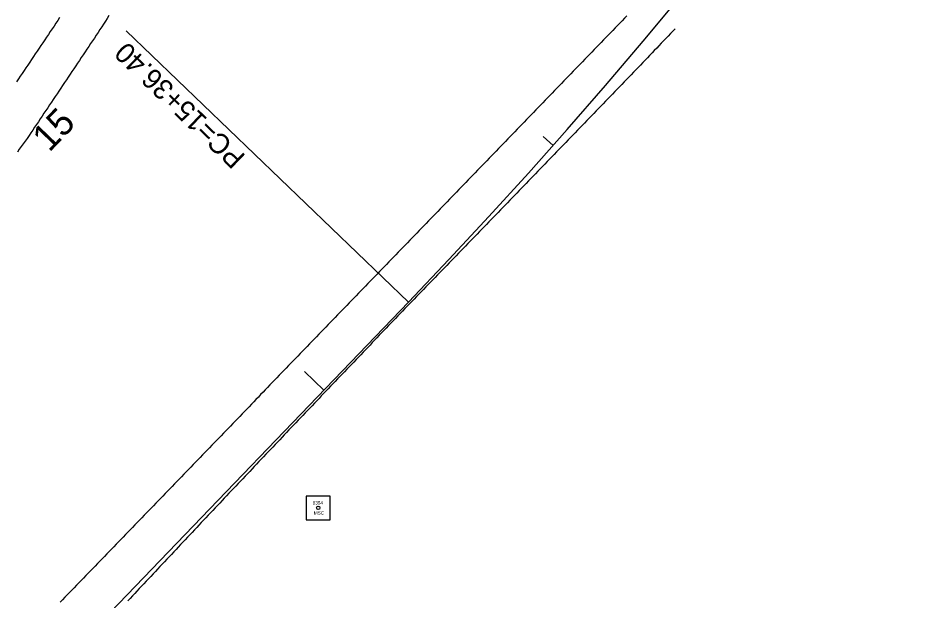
# Model space of a CAD drawing. Extents: x 205929 to 2357175, y -1785700 to 846739.
# Drawn here: x 2013213 to 2013479.6, y 821344.1 to 821517.6 of the extents above; entities that cross this region are included whole.
import ezdxf

# ---------------------------------------------------------------- set-up
doc = ezdxf.new("R2010")
doc.units = 0
for name, color, linetype in [('RD_HC_Cl', 7, 'Continuous'), ('RD_HC_Survey', 7, 'Continuous'), ('RD_HC_txCode', 7, 'Continuous'), ('RD_Sketch1', 7, 'Continuous'), ('RD_SMD_Locator', 7, 'Continuous')]:
    doc.layers.add(name, color=color, linetype=linetype)

msp = doc.modelspace()

# ---------------------------------------------------------------- linework, layer by layer
at = {"layer": 'RD_HC_Cl'}
for p, q in [((2013329.43, 821432.89), (2013245.32, 821513.78)), ((2013372.57, 821479.63), (2013369.57, 821482.28)), ((2012957.62, 821046.27), (2013329.43, 821432.89)), ((2013304.2, 821406.66), (2013298.44, 821412.21))]:
    msp.add_line(p, q, dxfattribs=at)
msp.add_arc((2012212.23, 822507.3), 1550, 316.11868, 35.79564, dxfattribs=at)
at = {"layer": 'RD_HC_Survey'}
msp.add_lwpolyline([(2013306.07, 821375.14), (2013299, 821375.14), (2013299, 821368.07), (2013306.07, 821368.07)], close=True, dxfattribs=at)
msp.add_circle((2013302.54, 821371.61), 0.5, dxfattribs=at)
at = {"layer": 'RD_Sketch1'}
for points in [[(2013225.48, 821517.69), (2013224.92, 821516.86), (2013224.36, 821516.03), (2013223.81, 821515.2), (2013223.25, 821514.37), (2013222.69, 821513.54), (2013222.13, 821512.71), (2013221.57, 821511.88), (2013221.02, 821511.05), (2013220.46, 821510.22), (2013219.9, 821509.39), (2013219.34, 821508.56), (2013218.78, 821507.73), (2013218.23, 821506.9), (2013217.67, 821506.07), (2013217.11, 821505.24), (2013216.55, 821504.41), (2013215.99, 821503.58), (2013215.44, 821502.75), (2013214.88, 821501.92), (2013214.32, 821501.09), (2013213.76, 821500.26), (2013213.2, 821499.43), (2013212.65, 821498.6)], [(2013240.18, 821518.33), (2013239.65, 821517.48), (2013239.11, 821516.63), (2013238.58, 821515.79), (2013238.04, 821514.95), (2013237.48, 821514.12), (2013236.93, 821513.29), (2013236.37, 821512.45), (2013235.82, 821511.62), (2013235.26, 821510.79), (2013234.7, 821509.96), (2013234.15, 821509.13), (2013233.59, 821508.3), (2013233.04, 821507.47), (2013232.48, 821506.64), (2013231.92, 821505.8), (2013231.37, 821504.97), (2013230.81, 821504.14), (2013230.26, 821503.31), (2013229.7, 821502.48), (2013229.15, 821501.65), (2013228.59, 821500.82), (2013228.03, 821499.98), (2013227.48, 821499.15), (2013226.92, 821498.32), (2013226.37, 821497.49), (2013225.81, 821496.66), (2013225.26, 821495.83), (2013224.7, 821495), (2013224.14, 821494.17), (2013223.59, 821493.33), (2013223.03, 821492.5), (2013222.48, 821491.67), (2013221.92, 821490.84), (2013221.36, 821490.01), (2013220.81, 821489.18), (2013220.25, 821488.35), (2013219.7, 821487.52), (2013219.14, 821486.68), (2013218.59, 821485.85), (2013218.03, 821485.02), (2013217.47, 821484.19), (2013216.92, 821483.36), (2013216.35, 821482.54), (2013215.77, 821481.72), (2013215.19, 821480.9), (2013214.61, 821480.09), (2013214.04, 821479.27), (2013213.46, 821478.46), (2013212.88, 821477.64)], [(2013394.52, 821518.22), (2013393.83, 821517.5), (2013393.13, 821516.78), (2013392.44, 821516.07), (2013391.74, 821515.35), (2013391.04, 821514.63), (2013390.35, 821513.91), (2013389.65, 821513.19), (2013388.96, 821512.47), (2013388.26, 821511.75), (2013387.57, 821511.04), (2013386.87, 821510.32), (2013386.18, 821509.6), (2013385.48, 821508.88), (2013384.78, 821508.16), (2013384.09, 821507.44), (2013383.39, 821506.72), (2013382.7, 821506.01), (2013382, 821505.29), (2013381.31, 821504.57), (2013380.61, 821503.85), (2013379.92, 821503.13), (2013379.22, 821502.41), (2013378.53, 821501.7), (2013377.83, 821500.98), (2013377.13, 821500.26), (2013376.44, 821499.54), (2013375.74, 821498.82), (2013375.05, 821498.1), (2013374.35, 821497.38), (2013373.66, 821496.67), (2013372.96, 821495.95), (2013372.27, 821495.23), (2013371.57, 821494.51), (2013370.88, 821493.79), (2013370.19, 821493.07), (2013369.49, 821492.35), (2013368.8, 821491.63), (2013368.1, 821490.91), (2013367.41, 821490.19), (2013366.71, 821489.47), (2013366.02, 821488.75), (2013365.33, 821488.03), (2013364.63, 821487.31), (2013363.94, 821486.59), (2013363.24, 821485.87), (2013362.55, 821485.15), (2013361.85, 821484.43), (2013361.16, 821483.71), (2013360.47, 821482.99), (2013359.77, 821482.27), (2013359.08, 821481.55), (2013358.38, 821480.83), (2013357.69, 821480.11), (2013356.99, 821479.39), (2013356.3, 821478.67), (2013355.61, 821477.95), (2013354.91, 821477.23), (2013354.22, 821476.51), (2013353.52, 821475.79), (2013352.83, 821475.07), (2013352.13, 821474.35), (2013351.44, 821473.63), (2013350.75, 821472.91), (2013350.05, 821472.2), (2013349.36, 821471.48), (2013348.66, 821470.76), (2013347.97, 821470.04), (2013347.28, 821469.32), (2013346.58, 821468.6), (2013345.89, 821467.88), (2013345.19, 821467.16), (2013344.5, 821466.44), (2013343.8, 821465.72), (2013343.1, 821465), (2013342.41, 821464.28), (2013341.71, 821463.57), (2013341.02, 821462.85), (2013340.32, 821462.13), (2013339.63, 821461.41), (2013338.93, 821460.69), (2013338.24, 821459.97), (2013337.54, 821459.25), (2013336.85, 821458.54), (2013336.15, 821457.82), (2013335.45, 821457.1), (2013334.76, 821456.38), (2013334.06, 821455.66), (2013333.37, 821454.94), (2013332.67, 821454.23), (2013331.98, 821453.51), (2013331.28, 821452.79), (2013330.59, 821452.07), (2013329.89, 821451.35), (2013329.19, 821450.63), (2013328.5, 821449.91), (2013327.8, 821449.2), (2013327.11, 821448.48), (2013326.41, 821447.76), (2013325.72, 821447.04), (2013325.02, 821446.32), (2013324.33, 821445.6), (2013323.63, 821444.89), (2013322.94, 821444.17), (2013322.24, 821443.45), (2013321.54, 821442.73), (2013320.85, 821442.01), (2013320.15, 821441.29), (2013319.46, 821440.57), (2013318.76, 821439.86), (2013318.07, 821439.14), (2013317.37, 821438.42), (2013316.68, 821437.7), (2013315.98, 821436.98), (2013315.28, 821436.26), (2013314.59, 821435.55), (2013313.89, 821434.83), (2013313.2, 821434.11), (2013312.5, 821433.39), (2013311.81, 821432.67), (2013311.11, 821431.95), (2013310.42, 821431.23), (2013309.72, 821430.52), (2013309.03, 821429.8), (2013308.33, 821429.08), (2013307.63, 821428.36), (2013306.94, 821427.64), (2013306.24, 821426.92), (2013305.55, 821426.2), (2013304.85, 821425.49), (2013304.16, 821424.77), (2013303.46, 821424.05), (2013302.77, 821423.33), (2013302.07, 821422.61), (2013301.37, 821421.89), (2013300.68, 821421.18), (2013299.98, 821420.46), (2013299.29, 821419.74), (2013298.59, 821419.02), (2013297.9, 821418.3), (2013297.2, 821417.58), (2013296.51, 821416.86), (2013295.81, 821416.15), (2013295.12, 821415.43), (2013294.42, 821414.71), (2013293.72, 821413.99), (2013293.03, 821413.27), (2013292.33, 821412.55), (2013291.64, 821411.83), (2013290.94, 821411.11), (2013290.25, 821410.39), (2013289.56, 821409.67), (2013288.86, 821408.95), (2013288.17, 821408.24), (2013287.47, 821407.52), (2013286.78, 821406.8), (2013286.09, 821406.08), (2013285.39, 821405.36), (2013284.7, 821404.64), (2013284, 821403.92), (2013283.31, 821403.2), (2013282.62, 821402.48), (2013281.92, 821401.76), (2013281.23, 821401.04), (2013280.53, 821400.32), (2013279.84, 821399.6), (2013279.14, 821398.88), (2013278.45, 821398.16), (2013277.76, 821397.44), (2013277.06, 821396.72), (2013276.37, 821396), (2013275.67, 821395.28), (2013274.98, 821394.56), (2013274.29, 821393.84), (2013273.59, 821393.12), (2013272.9, 821392.4), (2013272.2, 821391.68), (2013271.51, 821390.96), (2013270.82, 821390.24), (2013270.12, 821389.52), (2013269.43, 821388.8), (2013268.73, 821388.08), (2013268.04, 821387.36), (2013267.34, 821386.64), (2013266.65, 821385.92), (2013265.96, 821385.2), (2013265.26, 821384.48), (2013264.57, 821383.76), (2013263.87, 821383.04), (2013263.18, 821382.32), (2013262.48, 821381.6), (2013261.79, 821380.88), (2013261.09, 821380.17), (2013260.4, 821379.45), (2013259.71, 821378.73), (2013259.01, 821378.01), (2013258.32, 821377.29), (2013257.62, 821376.57), (2013256.93, 821375.85), (2013256.23, 821375.13), (2013255.54, 821374.41), (2013254.84, 821373.69), (2013254.15, 821372.97), (2013253.45, 821372.25), (2013252.76, 821371.53), (2013252.06, 821370.82), (2013251.37, 821370.1), (2013250.67, 821369.38), (2013249.98, 821368.66), (2013249.29, 821367.94), (2013248.59, 821367.22), (2013247.9, 821366.5), (2013247.2, 821365.78), (2013246.51, 821365.06), (2013245.81, 821364.34), (2013245.12, 821363.62), (2013244.42, 821362.9), (2013243.73, 821362.18), (2013243.03, 821361.46), (2013242.34, 821360.75), (2013241.64, 821360.03), (2013240.95, 821359.31), (2013240.25, 821358.59), (2013239.56, 821357.87), (2013238.87, 821357.15), (2013238.17, 821356.43), (2013237.48, 821355.71), (2013236.78, 821354.99), (2013236.09, 821354.27), (2013235.39, 821353.56), (2013234.69, 821352.84), (2013233.99, 821352.12), (2013233.3, 821351.4), (2013232.6, 821350.69), (2013231.9, 821349.97), (2013231.21, 821349.25), (2013230.51, 821348.54), (2013229.81, 821347.82), (2013229.12, 821347.1), (2013228.42, 821346.38), (2013227.72, 821345.67), (2013227.03, 821344.95), (2013226.33, 821344.23), (2013225.63, 821343.51)], [(2013408.97, 821514.37), (2013408.27, 821513.65), (2013407.58, 821512.93), (2013406.89, 821512.21), (2013406.19, 821511.49), (2013405.5, 821510.77), (2013404.8, 821510.05), (2013404.11, 821509.33), (2013403.42, 821508.61), (2013402.72, 821507.89), (2013402.03, 821507.17), (2013401.33, 821506.45), (2013400.64, 821505.73), (2013399.95, 821505.01), (2013399.25, 821504.29), (2013398.56, 821503.57), (2013397.86, 821502.85), (2013397.17, 821502.13), (2013396.48, 821501.41), (2013395.78, 821500.69), (2013395.09, 821499.97), (2013394.4, 821499.25), (2013393.7, 821498.53), (2013393.01, 821497.81), (2013392.31, 821497.09), (2013391.62, 821496.37), (2013390.93, 821495.65), (2013390.23, 821494.93), (2013389.54, 821494.21), (2013388.84, 821493.49), (2013388.15, 821492.77), (2013387.46, 821492.05), (2013386.76, 821491.33), (2013386.07, 821490.61), (2013385.37, 821489.89), (2013384.68, 821489.17), (2013383.99, 821488.45), (2013383.29, 821487.73), (2013382.6, 821487.01), (2013381.91, 821486.29), (2013381.21, 821485.57), (2013380.52, 821484.85), (2013379.82, 821484.13), (2013379.13, 821483.41), (2013378.43, 821482.69), (2013377.74, 821481.97), (2013377.05, 821481.25), (2013376.35, 821480.53), (2013375.66, 821479.81), (2013374.96, 821479.09), (2013374.27, 821478.38), (2013373.57, 821477.66), (2013372.88, 821476.94), (2013372.18, 821476.22), (2013371.49, 821475.5), (2013370.8, 821474.78), (2013370.1, 821474.06), (2013369.41, 821473.34), (2013368.71, 821472.62), (2013368.02, 821471.9), (2013367.32, 821471.18), (2013366.63, 821470.46), (2013365.93, 821469.74), (2013365.24, 821469.02), (2013364.55, 821468.3), (2013364.55, 821468.3), (2013363.85, 821467.58), (2013363.16, 821466.86), (2013362.46, 821466.14), (2013361.77, 821465.42), (2013361.07, 821464.7), (2013360.38, 821463.98), (2013359.68, 821463.27), (2013358.99, 821462.55), (2013358.3, 821461.83), (2013357.6, 821461.11), (2013356.91, 821460.39), (2013356.21, 821459.67), (2013355.52, 821458.95), (2013354.82, 821458.23), (2013354.13, 821457.51), (2013353.43, 821456.8), (2013352.73, 821456.08), (2013352.04, 821455.36), (2013351.34, 821454.64), (2013350.64, 821453.93), (2013349.95, 821453.21), (2013349.25, 821452.49), (2013348.55, 821451.77), (2013347.86, 821451.06), (2013347.16, 821450.34), (2013346.46, 821449.62), (2013345.77, 821448.9), (2013345.07, 821448.19), (2013344.37, 821447.47), (2013343.68, 821446.75), (2013342.98, 821446.03), (2013342.28, 821445.32), (2013341.59, 821444.6), (2013340.89, 821443.88), (2013340.19, 821443.16), (2013339.5, 821442.45), (2013338.8, 821441.73), (2013338.1, 821441.01), (2013337.41, 821440.29), (2013336.71, 821439.58), (2013336.02, 821438.86), (2013335.32, 821438.14), (2013334.62, 821437.43), (2013333.93, 821436.71), (2013333.23, 821435.99), (2013332.53, 821435.27), (2013331.84, 821434.56), (2013331.14, 821433.84), (2013330.44, 821433.12), (2013329.75, 821432.4), (2013329.05, 821431.69), (2013328.35, 821430.97), (2013327.66, 821430.25), (2013326.96, 821429.53), (2013326.27, 821428.81), (2013325.58, 821428.08), (2013324.89, 821427.36), (2013324.2, 821426.64), (2013323.51, 821425.92), (2013322.82, 821425.19), (2013322.13, 821424.47), (2013321.44, 821423.75), (2013320.74, 821423.03), (2013320.05, 821422.3), (2013320.05, 821422.3), (2013319.36, 821421.58), (2013318.67, 821420.86), (2013317.98, 821420.13), (2013317.29, 821419.41), (2013316.6, 821418.69), (2013315.91, 821417.97), (2013315.22, 821417.24), (2013314.53, 821416.52), (2013313.83, 821415.8), (2013313.14, 821415.07), (2013312.45, 821414.35), (2013311.76, 821413.63), (2013311.07, 821412.91), (2013310.38, 821412.18), (2013309.69, 821411.46), (2013309, 821410.74), (2013308.31, 821410.01), (2013307.62, 821409.29), (2013306.92, 821408.57), (2013306.23, 821407.85), (2013305.54, 821407.12), (2013304.85, 821406.4), (2013304.16, 821405.68), (2013303.47, 821404.96), (2013302.78, 821404.23), (2013302.09, 821403.51), (2013301.4, 821402.79), (2013300.71, 821402.06), (2013300.01, 821401.34), (2013299.32, 821400.62), (2013298.63, 821399.9), (2013297.94, 821399.17), (2013297.25, 821398.45), (2013296.57, 821397.72), (2013295.88, 821396.99), (2013295.19, 821396.27), (2013294.5, 821395.54), (2013293.82, 821394.82), (2013293.13, 821394.09), (2013292.44, 821393.36), (2013291.75, 821392.64), (2013291.07, 821391.91), (2013290.38, 821391.19), (2013289.69, 821390.46), (2013289, 821389.73), (2013288.32, 821389.01), (2013287.63, 821388.28), (2013286.94, 821387.56), (2013286.25, 821386.83), (2013285.57, 821386.1), (2013284.88, 821385.38), (2013284.19, 821384.65), (2013283.5, 821383.93), (2013282.81, 821383.2), (2013282.13, 821382.47), (2013281.44, 821381.75), (2013280.75, 821381.02), (2013280.06, 821380.3), (2013279.38, 821379.57), (2013278.69, 821378.84), (2013278, 821378.12), (2013277.31, 821377.39), (2013276.63, 821376.67), (2013275.94, 821375.94), (2013275.94, 821375.94), (2013275.25, 821375.22), (2013274.56, 821374.49), (2013273.88, 821373.76), (2013273.19, 821373.04), (2013272.5, 821372.31), (2013271.81, 821371.59), (2013271.13, 821370.86), (2013270.44, 821370.13), (2013269.75, 821369.4), (2013269.07, 821368.68), (2013268.38, 821367.95), (2013267.7, 821367.22), (2013267.01, 821366.49), (2013266.33, 821365.76), (2013265.65, 821365.03), (2013264.96, 821364.3), (2013264.28, 821363.57), (2013263.59, 821362.84), (2013262.91, 821362.12), (2013262.22, 821361.39), (2013261.54, 821360.66), (2013260.85, 821359.93), (2013260.17, 821359.2), (2013259.48, 821358.47), (2013258.8, 821357.74), (2013258.11, 821357.01), (2013257.43, 821356.28), (2013256.75, 821355.56), (2013256.06, 821354.83), (2013255.38, 821354.1), (2013254.69, 821353.37), (2013254.01, 821352.64), (2013253.32, 821351.91), (2013252.64, 821351.18), (2013251.95, 821350.45), (2013251.27, 821349.72), (2013250.58, 821349), (2013249.9, 821348.27), (2013249.22, 821347.54), (2013248.53, 821346.81), (2013247.85, 821346.08), (2013247.16, 821345.35), (2013246.48, 821344.62), (2013245.79, 821343.89)]]:
    msp.add_lwpolyline(points, dxfattribs=at)
at = {"layer": 'RD_SMD_Locator'}
msp.add_circle((2013302.54, 821371.61), 0.001, dxfattribs=at)

# ---------------------------------------------------------------- texts
at = {"layer": 'RD_HC_Cl'}
for s, height, rotation, p in [('PC=15+36.40', 6, 136.1187, (2013281.19, 821476.51)), ('15', 8, 46.1187, (2013222.37, 821477.37))]:
    msp.add_text(s, height=height, rotation=rotation, dxfattribs=at).set_placement(p)
at = {"layer": 'RD_HC_txCode'}
for s, p in [('8354', (2013300.91, 821372.61)), ('MSC', (2013301.22, 821369.61))]:
    msp.add_text(s, height=1, dxfattribs=at).set_placement(p)

doc.saveas('drawing.dxf')
